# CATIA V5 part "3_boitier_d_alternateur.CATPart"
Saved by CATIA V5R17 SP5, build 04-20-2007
Part number: 3_boitier_d_alternateur
Bounding box of the stored display mesh (mm): x -145.859 to 145.859, y -146 to 16, z -145.997 to 145.997
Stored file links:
  C:\Users\Frédéric\Documents\WF\STSCPI 09-11\Projets\Projet multiplicateur eolienne\Maquette eolienne\3_boitier_d_alternateur.CATPart
  C:\Users\Frédéric\Documents\WF\STSCPI 09-11\Projets\Projet multiplicateur eolienne\Maquette eolienne\Squelette_carter.CATPart
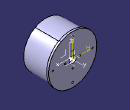
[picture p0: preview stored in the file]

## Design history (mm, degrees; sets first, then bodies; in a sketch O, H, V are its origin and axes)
AxisSystem1: origin (0, 0, 0), X (1, 0, 0), Y (0, 1, 0), Z (0, 0, 1)
Set1
  DatumCurve1
  DatumPoint1
  Line1: stored without definition
Body1 (main body)
Body2 "enveloppe alternateur"
  Sketch1 on YZ plane of AxisSystem1, origin (0, 0, 0), H (0, 1, 0), V (0, 0, 1)
    line L1 (-146, 135) -> (4, 135)
    line L2 (4, 135) -> (4, 131)
    line L3 (4, 131) -> (-146, 131)
    line L4 (-146, 131) -> (-146, 135)
    reference projected line E1 (4, 146) -> (4, -146) from edge [face of Shaft2 from Sketch2.L3 | face of Shaft2 from Sketch2.L4]
    distance H L3 = 131 {= Sketch2.length(L1)}
    length L4 = 4
    length L1 = 150
    horizontal: L1 H, L3 H
    vertical: L2 V, L4 V
    coincidence: L2 E1
  Shaft1: profile Sketch1, axis Sketch1.H, angle 360
Body3 "plaque en bout alternateur"
  Sketch2 on YZ plane of AxisSystem1, origin (0, 0, 0), H (0, 1, 0), V (0, 0, 1)
    line L1 (0, 0) -> (0, 131)
    line L2 (0, 131) -> (4, 131)
    line L3 (4, 131) -> (4, 146)
    line L4 (4, 146) -> (16, 146)
    line L5 (16, 146) -> (16, 0)
    point P5 (16, 0)
    line L6 (16, 0) -> (0, 0)
    length L1 = 131
    length L2 = 4
    length L5 = 146
    length L4 = 12
    vertical: L1 V, L3 V, L5 V
    horizontal: L2 H, L4 H, L6 H
    coincidence: P5 H
  Shaft2: profile Sketch2, axis Sketch2.L6, angle 360
  Sketch3 on face of Shaft2 from Sketch2.L1, origin (0, 0, 0), H (1, 0, 0), V (0, 0, 1)
    point P1 (0, 0)
    reference projected point E1 (0, 0) from vertex [YZ plane of AxisSystem1 | ZX plane of AxisSystem1 | XY plane of AxisSystem1]
    coincidence: E1 P1
  Hole1: placed by Sketch3, at (0, 0, 0) direction (0, 1, 0), diameter 42, through (limit type 6)
  Sketch4 on face of Shaft2 from Sketch2.L1, origin (0, 0, 0), H (1, 0, 0), V (0, 0, 1)
    point P1 (0, 46)
    distance P1 O = 46
    coincidence: P1 V
  Hole2: placed by Sketch4, at (0, 0, 46) direction (0, 1, 0), diameter 9, through (limit type 6)
  CircPattern1: of Hole2, instances 4, angular step 90, axis from edge [YZ plane of AxisSystem1 | XY plane of AxisSystem1]
  Sketch5 on face of Shaft2 from Sketch2.L5, origin (0, 16, 119), H (1, 0, 0), V (0, 0, -1)
    point P1 (0, 0)
    reference projected point E1 (0, 0) from Sketch6.P1
    coincidence: E1 P1
  Hole3: placed by Sketch5, at (0, 16, 119) direction (0, -1, 0), diameter 10.106, through (limit type 6), threaded "M12", thread diameter 12, thread depth 16, pitch 1.75
  CircPattern2: of Hole3, instances 4, angular step 90, axis from edge [YZ plane of AxisSystem1 | XY plane of AxisSystem1]
  Sketch6 "position taraudage pour tirant" on face of Shaft2 from Sketch2.L5, origin (0, 16, 0), H (-1, 0, 0), V (0, 0, 1)
    point P1 (0, 119)
    distance H P1 = 119
    coincidence: P1 V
